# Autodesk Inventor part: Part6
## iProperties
Shininess: 77.0
Length Units: 11269
Angle Units: 11279
Time Units: 11290
Mass Units: 11283
Length Display Precision: 3
Angle Display Precision: 2
Created: 2002-01
Part Number: Part6
Document SubType Name: Modeling
Designer: ***
Density: 0.0
Volumn: 0.0
Area: 0.0
PropertySet Name: Model Information
Control State: 0
Master: False
Checked Out: False
Author: ***
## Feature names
1. Revolution1
